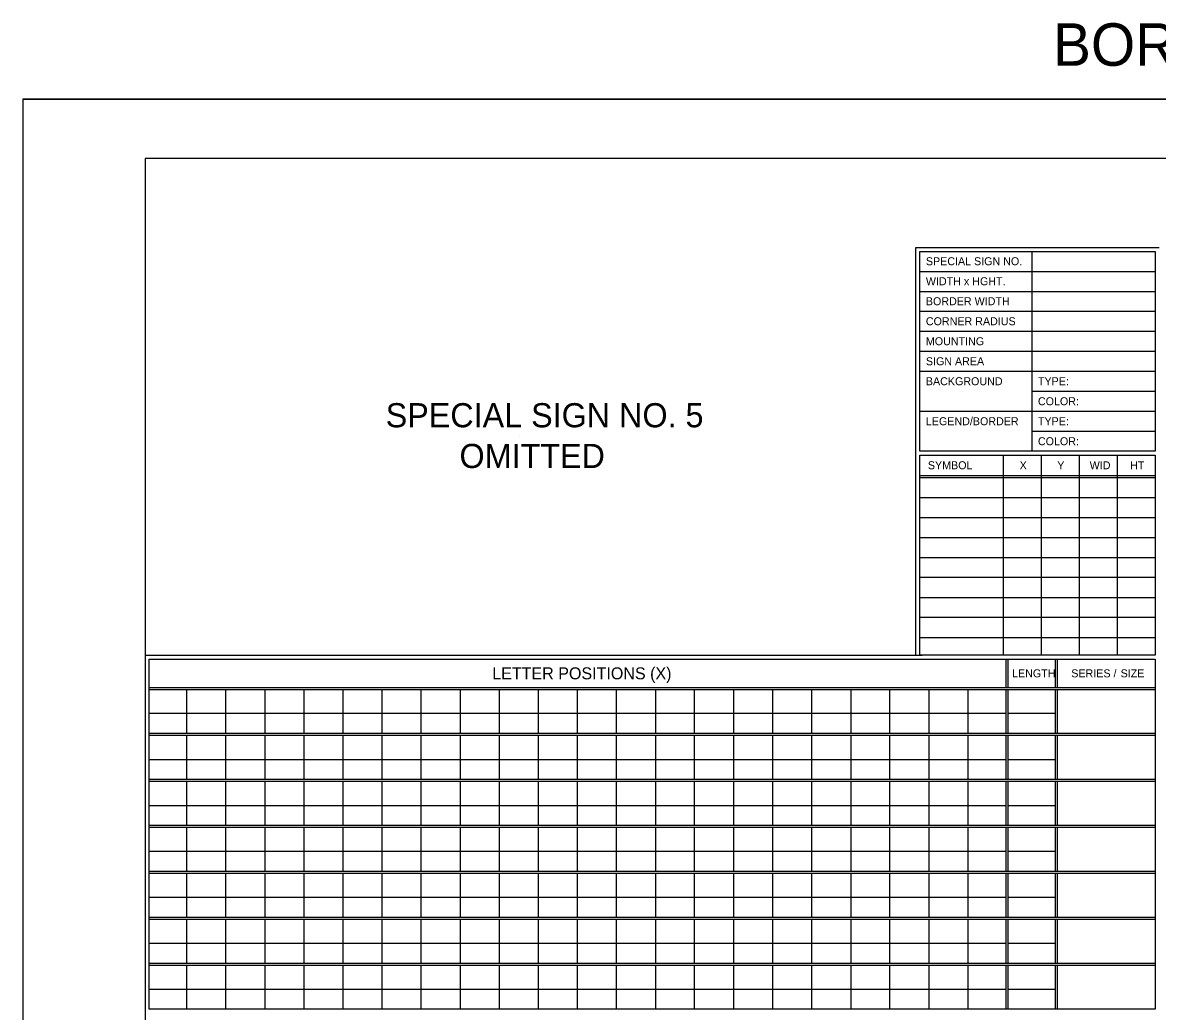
# Model space of a CAD drawing. Extents: x 2149934 to 2150188, y 145113 to 145238.
# Drawn here: x 2150010.5 to 2150076.2, y 145167.1 to 145224.4 of the extents above; entities that cross this region are included whole.
import ezdxf

# ---------------------------------------------------------------- set-up
doc = ezdxf.new("R2010")
doc.units = 0
for name, color, linetype in [('BORDER', 7, 'Continuous'), ('Level 1', 7, 'Continuous'), ('NON-PLOT', 7, 'Continuous'), ('PDF', 7, 'Continuous'), ('TEXT', 7, 'Continuous')]:
    doc.layers.add(name, color=color, linetype=linetype)

msp = doc.modelspace()

# ---------------------------------------------------------------- linework, layer by layer
at = {"layer": 'BORDER'}
for p, q in [((2150010.458, 145219.948), (2150174.061, 145219.948)), ((2150010.458, 145219.948), (2150010.458, 145114.088)), ((2150171.536, 145216.512), (2150017.557, 145216.512)), ((2150017.557, 145216.512), (2150017.557, 145117.388))]:
    msp.add_line(p, q, dxfattribs=at)
at = {"layer": 'Level 1'}
for p, q in [((2150062.21, 145211.34), (2150076.316, 145211.34)), ((2150068.935, 145211.108), (2150068.935, 145199.537)), ((2150062.442, 145209.949), (2150076.084, 145209.949)), ((2150062.442, 145208.789), (2150076.084, 145208.789)), ((2150062.442, 145207.653), (2150076.084, 145207.653)), ((2150062.442, 145206.494), (2150076.084, 145206.494)), ((2150062.442, 145205.334), (2150076.084, 145205.334)), ((2150062.442, 145204.175), (2150076.084, 145204.175)), ((2150068.935, 145203.015), (2150076.084, 145203.015)), ((2150062.442, 145201.856), (2150076.084, 145201.856)), ((2150068.935, 145200.696), (2150076.084, 145200.696)), ((2150062.442, 145187.705), (2150062.442, 145199.305)), ((2150062.442, 145199.305), (2150076.084, 145199.305)), ((2150067.272, 145199.299), (2150067.272, 145198.14)), ((2150069.475, 145199.299), (2150069.475, 145198.14)), ((2150071.678, 145199.299), (2150071.678, 145198.14)), ((2150073.881, 145199.299), (2150073.881, 145198.14)), ((2150076.084, 145199.305), (2150076.084, 145187.705)), ((2150062.442, 145198.14), (2150076.084, 145198.14)), ((2150067.272, 145198.14), (2150067.272, 145187.705)), ((2150069.475, 145198.14), (2150069.475, 145187.705)), ((2150071.678, 145198.14), (2150071.678, 145187.705)), ((2150073.881, 145198.14), (2150073.881, 145187.705)), ((2150062.442, 145198.024), (2150076.084, 145198.024)), ((2150062.442, 145196.864), (2150076.084, 145196.864)), ((2150062.442, 145195.705), (2150076.084, 145195.705)), ((2150062.442, 145194.545), (2150076.084, 145194.545)), ((2150062.442, 145193.386), (2150076.084, 145193.386)), ((2150062.442, 145192.227), (2150076.084, 145192.227)), ((2150062.442, 145191.067), (2150076.084, 145191.067)), ((2150062.442, 145189.908), (2150076.084, 145189.908)), ((2150062.442, 145188.748), (2150076.084, 145188.748)), ((2150017.557, 145187.705), (2150062.583, 145187.705)), ((2150076.084, 145187.705), (2150062.442, 145187.705)), ((2150067.426, 145187.473), (2150067.426, 145185.849)), ((2150067.542, 145187.473), (2150067.542, 145185.849)), ((2150070.29, 145187.473), (2150070.29, 145185.849)), ((2150070.405, 145187.473), (2150070.405, 145185.849)), ((2150017.789, 145185.849), (2150076.084, 145185.849)), ((2150017.789, 145185.733), (2150076.084, 145185.733)), ((2150019.946, 145185.733), (2150019.946, 145183.183)), ((2150022.218, 145185.733), (2150022.218, 145183.183)), ((2150024.491, 145185.733), (2150024.491, 145183.183)), ((2150026.74, 145185.733), (2150026.74, 145183.183)), ((2150029.013, 145185.733), (2150029.013, 145183.183)), ((2150031.262, 145185.733), (2150031.262, 145183.183)), ((2150033.535, 145185.733), (2150033.535, 145183.183)), ((2150035.808, 145185.733), (2150035.808, 145183.183)), ((2150038.057, 145185.733), (2150038.057, 145183.183)), ((2150040.329, 145185.733), (2150040.329, 145183.183)), ((2150042.579, 145185.733), (2150042.579, 145183.183)), ((2150044.851, 145185.733), (2150044.851, 145183.183)), ((2150047.124, 145185.733), (2150047.124, 145183.183)), ((2150049.373, 145185.733), (2150049.373, 145183.183)), ((2150051.646, 145185.733), (2150051.646, 145183.183)), ((2150053.895, 145185.733), (2150053.895, 145183.183)), ((2150056.168, 145185.733), (2150056.168, 145183.183)), ((2150058.441, 145185.733), (2150058.441, 145183.183)), ((2150060.69, 145185.733), (2150060.69, 145183.183)), ((2150062.962, 145185.733), (2150062.962, 145183.183)), ((2150065.212, 145185.733), (2150065.212, 145183.183)), ((2150067.426, 145185.733), (2150067.426, 145183.183)), ((2150067.542, 145185.733), (2150067.542, 145183.183)), ((2150070.29, 145185.733), (2150070.29, 145183.183)), ((2150070.405, 145185.733), (2150070.405, 145183.183)), ((2150017.789, 145184.342), (2150067.426, 145184.342)), ((2150067.542, 145184.342), (2150070.29, 145184.342)), ((2150017.789, 145183.183), (2150076.084, 145183.183)), ((2150017.789, 145183.067), (2150076.084, 145183.067)), ((2150019.946, 145183.067), (2150019.946, 145180.516)), ((2150022.218, 145183.067), (2150022.218, 145180.516)), ((2150024.491, 145183.067), (2150024.491, 145180.516)), ((2150026.74, 145183.067), (2150026.74, 145180.516)), ((2150029.013, 145183.067), (2150029.013, 145180.516)), ((2150031.262, 145183.067), (2150031.262, 145180.516)), ((2150033.535, 145183.067), (2150033.535, 145180.516)), ((2150035.808, 145183.067), (2150035.808, 145180.516)), ((2150038.057, 145183.067), (2150038.057, 145180.516)), ((2150040.329, 145183.067), (2150040.329, 145180.516)), ((2150042.579, 145183.067), (2150042.579, 145180.516)), ((2150044.851, 145183.067), (2150044.851, 145180.516)), ((2150047.124, 145183.067), (2150047.124, 145180.516)), ((2150049.373, 145183.067), (2150049.373, 145180.516)), ((2150051.646, 145183.067), (2150051.646, 145180.516)), ((2150053.895, 145183.067), (2150053.895, 145180.516)), ((2150056.168, 145183.067), (2150056.168, 145180.516)), ((2150058.441, 145183.067), (2150058.441, 145180.516)), ((2150060.69, 145183.067), (2150060.69, 145180.516)), ((2150062.962, 145183.067), (2150062.962, 145180.516)), ((2150065.212, 145183.067), (2150065.212, 145180.516)), ((2150067.426, 145183.067), (2150067.426, 145180.516)), ((2150067.542, 145183.067), (2150067.542, 145180.516)), ((2150070.29, 145183.067), (2150070.29, 145180.516)), ((2150070.405, 145183.067), (2150070.405, 145180.516)), ((2150017.789, 145181.675), (2150067.426, 145181.675)), ((2150067.542, 145181.675), (2150070.29, 145181.675)), ((2150017.789, 145180.516), (2150076.084, 145180.516)), ((2150017.789, 145180.4), (2150076.084, 145180.4)), ((2150019.946, 145180.4), (2150019.946, 145177.849)), ((2150022.218, 145180.4), (2150022.218, 145177.849)), ((2150024.491, 145180.4), (2150024.491, 145177.849)), ((2150026.74, 145180.4), (2150026.74, 145177.849)), ((2150029.013, 145180.4), (2150029.013, 145177.849)), ((2150031.262, 145180.4), (2150031.262, 145177.849)), ((2150033.535, 145180.4), (2150033.535, 145177.849)), ((2150035.808, 145180.4), (2150035.808, 145177.849)), ((2150038.057, 145180.4), (2150038.057, 145177.849)), ((2150040.329, 145180.4), (2150040.329, 145177.849)), ((2150042.579, 145180.4), (2150042.579, 145177.849)), ((2150044.851, 145180.4), (2150044.851, 145177.849)), ((2150047.124, 145180.4), (2150047.124, 145177.849)), ((2150049.373, 145180.4), (2150049.373, 145177.849)), ((2150051.646, 145180.4), (2150051.646, 145177.849)), ((2150053.895, 145180.4), (2150053.895, 145177.849)), ((2150056.168, 145180.4), (2150056.168, 145177.849)), ((2150058.441, 145180.4), (2150058.441, 145177.849)), ((2150060.69, 145180.4), (2150060.69, 145177.849)), ((2150062.962, 145180.4), (2150062.962, 145177.849)), ((2150065.212, 145180.4), (2150065.212, 145177.849)), ((2150067.426, 145180.4), (2150067.426, 145177.849)), ((2150067.542, 145180.4), (2150067.542, 145177.849)), ((2150070.29, 145180.4), (2150070.29, 145177.849)), ((2150070.405, 145180.4), (2150070.405, 145177.849)), ((2150017.789, 145179.008), (2150067.426, 145179.008)), ((2150067.542, 145179.008), (2150070.29, 145179.008)), ((2150017.789, 145177.849), (2150076.084, 145177.849)), ((2150017.789, 145177.733), (2150076.084, 145177.733)), ((2150019.946, 145177.733), (2150019.946, 145175.182)), ((2150022.218, 145177.733), (2150022.218, 145175.182)), ((2150024.491, 145177.733), (2150024.491, 145175.182)), ((2150026.74, 145177.733), (2150026.74, 145175.182)), ((2150029.013, 145177.733), (2150029.013, 145175.182)), ((2150031.262, 145177.733), (2150031.262, 145175.182)), ((2150033.535, 145177.733), (2150033.535, 145175.182)), ((2150035.808, 145177.733), (2150035.808, 145175.182)), ((2150038.057, 145177.733), (2150038.057, 145175.182)), ((2150040.329, 145177.733), (2150040.329, 145175.182)), ((2150042.579, 145177.733), (2150042.579, 145175.182)), ((2150044.851, 145177.733), (2150044.851, 145175.182)), ((2150047.124, 145177.733), (2150047.124, 145175.182)), ((2150049.373, 145177.733), (2150049.373, 145175.182)), ((2150051.646, 145177.733), (2150051.646, 145175.182)), ((2150053.895, 145177.733), (2150053.895, 145175.182)), ((2150056.168, 145177.733), (2150056.168, 145175.182)), ((2150058.441, 145177.733), (2150058.441, 145175.182)), ((2150060.69, 145177.733), (2150060.69, 145175.182)), ((2150062.962, 145177.733), (2150062.962, 145175.182)), ((2150065.212, 145177.733), (2150065.212, 145175.182)), ((2150067.426, 145177.733), (2150067.426, 145175.182)), ((2150067.542, 145177.733), (2150067.542, 145175.182)), ((2150070.29, 145177.733), (2150070.29, 145175.182)), ((2150070.405, 145177.733), (2150070.405, 145175.182)), ((2150017.789, 145176.342), (2150067.426, 145176.342)), ((2150067.542, 145176.342), (2150070.29, 145176.342)), ((2150017.789, 145175.182), (2150076.084, 145175.182)), ((2150017.789, 145175.066), (2150076.084, 145175.066)), ((2150019.946, 145175.066), (2150019.946, 145172.515)), ((2150022.218, 145175.066), (2150022.218, 145172.515)), ((2150024.491, 145175.066), (2150024.491, 145172.515)), ((2150026.74, 145175.066), (2150026.74, 145172.515)), ((2150029.013, 145175.066), (2150029.013, 145172.515)), ((2150031.262, 145175.066), (2150031.262, 145172.515)), ((2150033.535, 145175.066), (2150033.535, 145172.515)), ((2150035.808, 145175.066), (2150035.808, 145172.515)), ((2150038.057, 145175.066), (2150038.057, 145172.515)), ((2150040.329, 145175.066), (2150040.329, 145172.515)), ((2150042.579, 145175.066), (2150042.579, 145172.515)), ((2150044.851, 145175.066), (2150044.851, 145172.515)), ((2150047.124, 145175.066), (2150047.124, 145172.515)), ((2150049.373, 145175.066), (2150049.373, 145172.515)), ((2150051.646, 145175.066), (2150051.646, 145172.515)), ((2150053.895, 145175.066), (2150053.895, 145172.515)), ((2150056.168, 145175.066), (2150056.168, 145172.515)), ((2150058.441, 145175.066), (2150058.441, 145172.515)), ((2150060.69, 145175.066), (2150060.69, 145172.515)), ((2150062.962, 145175.066), (2150062.962, 145172.515)), ((2150065.212, 145175.066), (2150065.212, 145172.515)), ((2150067.426, 145175.066), (2150067.426, 145172.515)), ((2150067.542, 145175.066), (2150067.542, 145172.515)), ((2150070.29, 145175.066), (2150070.29, 145172.515)), ((2150070.405, 145175.066), (2150070.405, 145172.515)), ((2150017.789, 145173.675), (2150067.426, 145173.675)), ((2150067.542, 145173.675), (2150070.29, 145173.675)), ((2150017.789, 145172.515), (2150076.084, 145172.515)), ((2150017.789, 145172.399), (2150076.084, 145172.399)), ((2150019.946, 145172.399), (2150019.946, 145169.849)), ((2150022.218, 145172.399), (2150022.218, 145169.849)), ((2150024.491, 145172.399), (2150024.491, 145169.849)), ((2150026.74, 145172.399), (2150026.74, 145169.849)), ((2150029.013, 145172.399), (2150029.013, 145169.849)), ((2150031.262, 145172.399), (2150031.262, 145169.849)), ((2150033.535, 145172.399), (2150033.535, 145169.849)), ((2150035.808, 145172.399), (2150035.808, 145169.849)), ((2150038.057, 145172.399), (2150038.057, 145169.849)), ((2150040.329, 145172.399), (2150040.329, 145169.849)), ((2150042.579, 145172.399), (2150042.579, 145169.849)), ((2150044.851, 145172.399), (2150044.851, 145169.849)), ((2150047.124, 145172.399), (2150047.124, 145169.849)), ((2150049.373, 145172.399), (2150049.373, 145169.849)), ((2150051.646, 145172.399), (2150051.646, 145169.849)), ((2150053.895, 145172.399), (2150053.895, 145169.849)), ((2150056.168, 145172.399), (2150056.168, 145169.849)), ((2150058.441, 145172.399), (2150058.441, 145169.849)), ((2150060.69, 145172.399), (2150060.69, 145169.849)), ((2150062.962, 145172.399), (2150062.962, 145169.849)), ((2150065.212, 145172.399), (2150065.212, 145169.849)), ((2150067.426, 145172.399), (2150067.426, 145169.849)), ((2150067.542, 145172.399), (2150067.542, 145169.849)), ((2150070.29, 145172.399), (2150070.29, 145169.849)), ((2150070.405, 145172.399), (2150070.405, 145169.849)), ((2150017.789, 145171.008), (2150067.426, 145171.008)), ((2150067.542, 145171.008), (2150070.29, 145171.008)), ((2150017.789, 145169.849), (2150076.084, 145169.849)), ((2150017.789, 145169.733), (2150076.084, 145169.733)), ((2150019.946, 145169.733), (2150019.946, 145167.182)), ((2150022.218, 145169.733), (2150022.218, 145167.182)), ((2150024.491, 145169.733), (2150024.491, 145167.182)), ((2150026.74, 145169.733), (2150026.74, 145167.182)), ((2150029.013, 145169.733), (2150029.013, 145167.182)), ((2150031.262, 145169.733), (2150031.262, 145167.182)), ((2150033.535, 145169.733), (2150033.535, 145167.182)), ((2150035.808, 145169.733), (2150035.808, 145167.182)), ((2150038.057, 145169.733), (2150038.057, 145167.182)), ((2150040.329, 145169.733), (2150040.329, 145167.182)), ((2150042.579, 145169.733), (2150042.579, 145167.182)), ((2150044.851, 145169.733), (2150044.851, 145167.182)), ((2150047.124, 145169.733), (2150047.124, 145167.182)), ((2150049.373, 145169.733), (2150049.373, 145167.182)), ((2150051.646, 145169.733), (2150051.646, 145167.182)), ((2150053.895, 145169.733), (2150053.895, 145167.182)), ((2150056.168, 145169.733), (2150056.168, 145167.182)), ((2150058.441, 145169.733), (2150058.441, 145167.182)), ((2150060.69, 145169.733), (2150060.69, 145167.182)), ((2150062.962, 145169.733), (2150062.962, 145167.182)), ((2150065.212, 145169.733), (2150065.212, 145167.182)), ((2150067.426, 145169.733), (2150067.426, 145167.182)), ((2150067.542, 145169.733), (2150067.542, 145167.182)), ((2150070.29, 145169.733), (2150070.29, 145167.182)), ((2150070.405, 145169.733), (2150070.405, 145167.182)), ((2150017.789, 145168.341), (2150067.426, 145168.341)), ((2150067.542, 145168.341), (2150070.29, 145168.341))]:
    msp.add_line(p, q, dxfattribs=at)
msp.add_lwpolyline([(2150062.21, 145187.705), (2150062.21, 145211.34)], dxfattribs=at)
for points in [[(2150062.442, 145211.108), (2150076.084, 145211.108), (2150076.084, 145199.537), (2150062.442, 145199.537)], [(2150017.789, 145187.473), (2150076.084, 145187.473), (2150076.084, 145167.182), (2150017.789, 145167.182)]]:
    msp.add_lwpolyline(points, close=True, dxfattribs=at)
at = {"layer": 'NON-PLOT'}
msp.add_line((2150039.27, 145200.445), (2150039.27, 145200.445), dxfattribs=at)
at = {"layer": 'PDF'}
msp.add_lwpolyline([(2150010.458, 145114.088), (2150174.061, 145114.088), (2150174.061, 145219.948), (2150010.458, 145219.948)], close=True, dxfattribs=at)

# ---------------------------------------------------------------- texts
at = {"layer": 'Level 1'}
for s, height, p in [('SPECIAL SIGN NO.', 0.46374, (2150062.79, 145210.32)), ('WIDTH x HGHT.', 0.46374, (2150062.79, 145209.16)), ('BORDER WIDTH', 0.46374, (2150062.79, 145208.001)), ('CORNER RADIUS', 0.46374, (2150062.79, 145206.841)), ('MOUNTING', 0.4637, (2150062.79, 145205.682)), ('SIGN AREA', 0.4638, (2150062.79, 145204.522)), ('BACKGROUND', 0.4637, (2150062.79, 145203.363)), ('TYPE:', 0.4637, (2150069.283, 145203.363)), ('COLOR:', 0.4637, (2150069.283, 145202.203)), ('LEGEND/BORDER', 0.46374, (2150062.79, 145201.044)), ('TYPE:', 0.4637, (2150069.283, 145201.044)), ('COLOR:', 0.4637, (2150069.283, 145199.885)), ('SYMBOL', 0.4637, (2150062.906, 145198.493)), ('X', 0.464, (2150068.223, 145198.488)), ('Y', 0.464, (2150070.403, 145198.488)), ('WID', 0.4637, (2150072.281, 145198.488)), ('HT', 0.4637, (2150074.623, 145198.488)), ('LETTER POSITIONS (X)', 0.69555, (2150037.664, 145186.313)), ('LENGTH', 0.4638, (2150067.783, 145186.429)), ('LENGTH', 0.4638, (2150067.783, 145186.429)), ('SERIES /', 0.4638, (2150071.216, 145186.429)), ('SIZE', 0.4638, (2150074.074, 145186.429))]:
    msp.add_text(s, height=height, dxfattribs=at).set_placement(p)
at = {"layer": 'TEXT'}
for s, height, p in [('BORDER AND REPORT 70 SCALE', 2.46401, (2150070.157, 145221.883)), ('SPECIAL SIGN NO. 5', 1.4, (2150031.49, 145200.925)), ('OMITTED', 1.4, (2150035.768, 145198.565))]:
    msp.add_text(s, height=height, dxfattribs=at).set_placement(p)

doc.saveas('drawing.dxf')
